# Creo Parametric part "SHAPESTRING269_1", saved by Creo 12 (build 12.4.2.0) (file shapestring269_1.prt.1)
Units: Custom; MM, KILOGRAM, SECS

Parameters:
  PTC_WM_ITERATION = "0"
  PTC_WM_VERSION = "-.0"
  PTC_WM_LIFECYCLE_STATE = "In Work"
  PTC_WM_LIFECYCLE = "MO_CADDocument"
  PTC_WM_CREATED_BY = "Maximilian Roepper (Z0017RMS: MO)"
  PTC_WM_CREATED_ON = "18-Sep-26 11:36:42 AM"
  PTC_WM_MODIFIED_BY = "Maximilian Roepper (Z0017RMS: MO)"
  PTC_WM_MODIFIED_ON = "18-Sep-26 11:36:46 AM"
  PDMLINKNUMBER = "PDM000071454859"
  PTC_WM_NAME = "shapestring269_1.prt"
  PTC_WM_NUMBER = "PDM000071454859"

Other parameters: WEIGHT, WEIGHT_FACTOR, WEIGHT_ADD, _MASS_TEMP, _DIFF_TEMP, MC_ERRORS, SUPPLIER

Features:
  1. coordinate system
  2. datum plane "PRT_YZ"
  3. datum plane "PRT_XY"
  4. datum plane "PRT_XZ"
  5. coordinate system
  6. datum axis
  7. datum axis
  8. datum axis
  9. coordinate system
  10. imported feature
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
Other named items: PRT, SIEMENS_MO, DRW_VIEW_ORG, PRT_X, PRT_Y, PRT_Z, CS0, ROUGH_GROB

Layers: 00_STD_CSYS-KSYS, 01_STD_PLANES-EBENEN, 02_STD_AXES-ACHSEN, 03_STD_CSYS-KSYS, 24_IMPORT_FEAT-IMPORT_KE, WHITE

Surfaces: 1 plane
